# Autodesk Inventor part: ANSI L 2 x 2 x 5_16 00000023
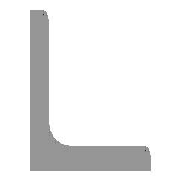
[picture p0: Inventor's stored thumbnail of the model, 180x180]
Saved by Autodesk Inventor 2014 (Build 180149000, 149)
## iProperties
_FrameMemberDoc: Frame Member File
_Version: 13.0.0
_CCFamilyMember: 12
_CCFamilyDisplayName: ANSI L (Equal angles) - Angle Steel
Created: 2007-02
Part Number: ANSI L 2 x 2 x 5_16 00000023
Material: Steel, Mild
Document SubType Name: Modeling
Standard: ANSI
Designer: Autodesk, Inc.
Size Designation: L 2 x 2 x 5/16
Stock Number: L 2 x 2 x 5/16
Density: 7.86 g/cm^3
Description: Angle Steel
Standards Organization: ANSI
Language: en-US
Categories: <MemberInstance><Categories><Category DisplayName="Structural Shapes" InternalName="089c4875-fa83-4c05-b084-43b9cc11f5ed" Mnemonic="GRDR"><CategoryParameter Dis
Mass: 4137.91 g
Surface Area: 1406.57 cm^2
Volume: 526.452 cm^3
Appearance: Steel
IsCustomPart: 1
G_L: 28.000 in
G_W: 2.000 in
G_H: 2.000 in
+CC282AAB-4AD7-4025-8A75-6B04D7C1D3BB+CUTDETAIL1: Notch
+4B234BBB-5376-4DC8-859A-8989FA403DFD+CUTDETAIL2: Notch
Author: Autodesk, Inc.
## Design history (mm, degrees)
node "Start plane"
node "End plane"
sketch "Sketch"
  geometry: L1 (50.8, 0)-(0, 0); L2 (0, 0)-(0, 50.8); L3 (0, 50.8)-(4.889, 50.8); L4 (7.937, 47.752)-(7.937, 14.288); L5 (14.287, 7.938)-(47.752, 7.938); L6 (50.8, 4.89)-(50.8, 0); L7 (0, -11.041)-(0, 31.538); L8 (-11.041, 0)-(31.538, 0); L9 (0, 63.926)-(0, -23.536) reference; L10 (-23.536, 0)-(63.926, 0) reference; A1 r 6.35 centre (14.287, 14.288) between (7.937, 14.288) and (14.287, 7.938); A2 r 3.048 centre (4.889, 47.752) between (7.937, 47.752) and (4.889, 50.8); A3 r 3.048 centre (47.752, 4.89) between (50.8, 4.89) and (47.752, 7.938); 3 further points
  constraints: 16 end point, 6 point on circle, 6 point on line, 6 tangent, 4 parallel, 3 centre point, 2 collinear, 1 equal radius, 1 horizontal, 1 perpendicular
  dimensions: "d0" = 50.8 distance between parallel lines of L6 L2 (= G_H); "d1" = 50.8 distance between parallel lines of L3 L1 (= G_H); "d2" = 7.9375 distance between parallel lines of L2 L4 (= G_T); "d3" = 7.9375 distance between parallel lines of L1 L5 (= G_T); "d10" = 0 distance between parallel lines of L7 L2 (computed from ex); "d11" = 0 distance between parallel lines of L8 L1 (computed from d10); "d14" = 6.35 radius of A1 (= G_IR); "d15" = 3.048 radius of A2 (= G_ER)
extrude "Body" new body sketch "Sketch" stored distance "d4" = 711.2 (= G_L); taper "d5" = 0 deg
node "Driven Length"
  sketch "Sketch5"
    geometry: L1 (0, 0)-(10, 0) reference
    constraints: 2 end point, 1 horizontal
  workplane "Work Plane7"
  sketch "Sketch6"
    geometry: L1 (-2, 0)-(12, 0) reference; L2 (-2, 711.2)-(12, 711.2) reference
    dimensions: "d21" = 711.2 distance between parallel lines of L1 L2 (derived)
workplane "Work Plane3"
workplane "Work Plane4"
derived "ANSI L 2 x 2 x 1_4 00000003.ipt"
  sketch "Sketch_1"
    geometry: L1 (50.8, 0)-(0, 0) reference; L2 (0, 0)-(0, 50.8) reference; L3 (0, 50.8)-(3.302, 50.8) reference; L4 (6.35, 47.752)-(6.35, 12.7) reference; L5 (12.7, 6.35)-(47.752, 6.35) reference; L6 (50.8, 3.302)-(50.8, 0) reference; L7 (0, -11.041)-(0, 31.538) reference; L8 (-11.041, 0)-(31.538, 0) reference; L9 (0, 63.926)-(0, -23.536) reference; L10 (-23.536, 0)-(63.926, 0) reference; A1 r 6.35 centre (12.7, 12.7) between (6.35, 12.7) and (12.7, 6.35) reference; A2 r 3.048 centre (3.302, 47.752) between (6.35, 47.752) and (3.302, 50.8) reference; A3 r 3.048 centre (47.752, 3.302) between (50.8, 3.302) and (47.752, 6.35) reference; 3 further points
extrude "Extrusion2" cut sketch "Sketch_1" stored distance "d16" = 3.302; taper "d17" = 0 deg
workplane "Work Plane5"
workplane "Work Plane6"
derived "ANSI L 2 x 2 x 1_4 00000004.ipt"
  sketch "Sketch_2"
    geometry: L1 (50.8, 0)-(0, 0) reference; L2 (0, 0)-(0, 50.8) reference; L3 (0, 50.8)-(3.302, 50.8) reference; L4 (6.35, 47.752)-(6.35, 12.7) reference; L5 (12.7, 6.35)-(47.752, 6.35) reference; L6 (50.8, 3.302)-(50.8, 0) reference; L7 (0, -11.041)-(0, 31.538) reference; L8 (-11.041, 0)-(31.538, 0) reference; L9 (0, 63.926)-(0, -23.536) reference; L10 (-23.536, 0)-(63.926, 0) reference; A1 r 6.35 centre (12.7, 12.7) between (6.35, 12.7) and (12.7, 6.35) reference; A2 r 3.048 centre (3.302, 47.752) between (6.35, 47.752) and (3.302, 50.8) reference; A3 r 3.048 centre (47.752, 3.302) between (50.8, 3.302) and (47.752, 6.35) reference; 3 further points
extrude "Extrusion3" cut sketch "Sketch_2" stored distance "d18" = 3.302; taper "d19" = 0 deg
body "Solid1"
other parameters: "G_H" = 50.8 [user parameter; used in 2 equation terms], "G_T" = 7.9375 [user parameter; used in 2 equation terms], "G_ER" = 3.048 [user parameter; used in 1 equation term], "G_IR" = 6.35 [user parameter; used in 1 equation term], "G_L" = 711.2 (= d21) [user parameter; used in 1 equation term], "ex" = 0 [user parameter; used in 1 equation term], "G_OFFSET_START" = 0 [user parameter; used in 1 equation term], "G_OFFSET_END" = 0 [user parameter; used in 1 equation term], "d12" = 0 (computed from G_OFFSET_START), "d13" = 711.2 (= G_OFFSET_END + B_L), "B_L" = 711.2 [user parameter; used in 1 equation term], "d20" = 90 deg, "MAS" = 0.58336 [user parameter]
